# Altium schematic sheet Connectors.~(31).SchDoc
size A4
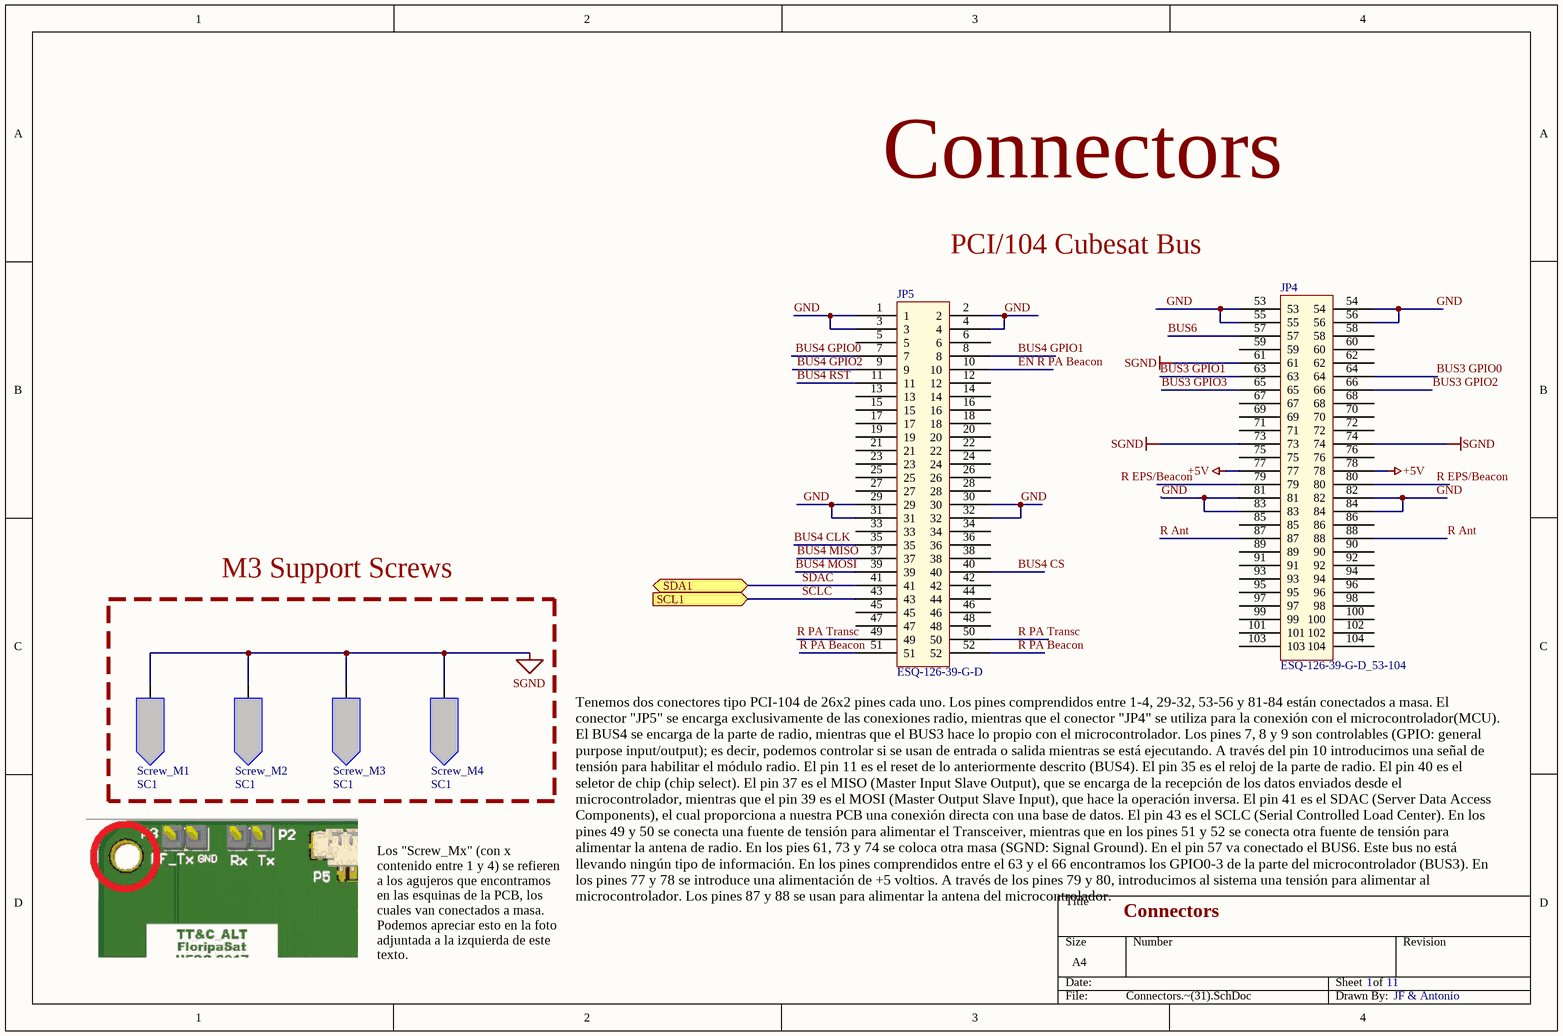
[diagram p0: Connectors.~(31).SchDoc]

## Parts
JP4  ESQ-126-39-G-D_53-104  [ESQ-126-39-G-D_53_104]
JP5  ESQ-126-39-G-D  [ESQ-126-39-G-D]
Screw_M1  SC1  [Screw_M3]
Screw_M2  SC1  [Screw_M3]
Screw_M3  SC1  [Screw_M3]
Screw_M4  SC1  [Screw_M3]

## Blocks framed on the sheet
M3 Support Screws: Screw_M1-Screw_M4

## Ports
SCL1 (in), SDA1 (bidir)

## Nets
+5V: JP4.77 JP4.78
SGND: JP4.61 JP4.73 JP4.74 Screw_M1.1 Screw_M2.1 Screw_M3.1 Screw_M4.1
BUS3 GPIO0: JP4.64
BUS3 GPIO1: JP4.63
BUS3 GPIO2: JP4.66
BUS3 GPIO3: JP4.65
BUS4 CLK: JP5.35
BUS4 CS: JP5.40
BUS4 GPIO0: JP5.7
BUS4 GPIO1: JP5.8
BUS4 GPIO2: JP5.9
BUS4 MISO: JP5.37
BUS4 MOSI: JP5.39
BUS4 RST: JP5.11
BUS6: JP4.57
EN R PA Beacon: JP5.10
GND: JP4.53 JP4.54 JP4.55 JP4.56 JP4.81 JP4.82 JP4.83 JP4.84 JP5.1 JP5.2 JP5.3 JP5.4 JP5.29 JP5.30 JP5.31 JP5.32
R Ant: JP4.87 JP4.88
R EPS/Beacon: JP4.80
R PA Beacon: JP5.51 JP5.52
R PA Transc: JP5.49 JP5.50
SCLC: JP5.43 ; port SCL1
SDAC: JP5.41 ; port SDA1

Not connected (* = marked no-connect by the designer): JP4 58 59 60 62 67 68 69 70 71 72 75 76 79 85 86 89 90 91 92 93 94 95 96 97 98 99 100 101 102 103 104; JP5 5 6 12 13 14 15 16 17 18 19 20 21 22 23 24 25 26 27 28 33 34 36 38 42 44 45 46 47 48

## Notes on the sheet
- Connectors
- PCI/104 Cubesat Bus
- Los "Screw_Mx" (con x contenido entre 1 y 4) se refieren a los agujeros que encontramos en las esquinas de la PCB, los cuales van conectados a masa. Podemos apreciar esto en la foto adjuntada a la izquierda de este texto.
- Tenemos dos conectores tipo PCI-104 de 26x2 pines cada uno. Los pines comprendidos entre 1-4, 29-32, 53-56 y 81-84 están conectados a masa. El conector "JP5" se encarga exclusivamente de las conexiones radio, mientras que el conector "JP4" se utiliza para la conexión con el microcontrolador(MCU). El BUS4 se encarga de la parte de radio, mientras que el BUS3 hace lo propio con el microcontrolador. Los pines 7, 8 y 9 son controlables (GPIO: general purpose input/output); es decir, podemos controlar si se usan de entrada o salida mientras se está ejecutando. A través del pin 10 introducimos una señal de tensión para habilitar el módulo radio. El pin 11 es el reset de lo anteriormente descrito (BUS4). El pin 35 es el reloj de la parte de radio. El pin 40 es el seletor de chip (chip select). El pin 37 es el MISO (Master Input Slave Output), que se encarga de la recepción de los datos enviados desde el microcontrolador, mientras que el pin 39 es el MOSI (Master Output Slave Input), que hace la operación inversa. El pin 41 es el SDAC (Server Data Access Components), el cual proporciona a nuestra PCB una conexión directa con una base de datos. El pin 43 es el SCLC (Serial Controlled Load Center). En los pines 49 y 50 se conecta una fuente de tensión para alimentar el Transceiver, mientras que en los pines 51 y 52 se conecta otra fuente de tensión para alimentar la antena de radio. En los pies 61, 73 y 74 se coloca otra masa (SGND: Signal Ground). En el pin 57 va conectado el BUS6. Este bus no está llevando ningún tipo de información. En los pines comprendidos entre el 63 y el 66 encontramos los GPIO0-3 de la parte del microcontrolador (BUS3). En los pines 77 y 78 se introduce una alimentación de +5 voltios. A través de los pines 79 y 80, introducimos al sistema una tensión para alimentar al microcontrolador. Los pines 87 y 88 se usan para alimentar la antena del microcontrolador.
- 1
- 11
- JF & Antonio
- Labels drawn without touching a wire or pin: R EPS/Beacon

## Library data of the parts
JP4 = ESQ-126-39-G-D_53-104: Cubesat Header Connector; Shop: es.rs-online.com; Localización: Último cajón cajonera blanca entre Pablo y Luis; Reference: 254-6132
JP5 = ESQ-126-39-G-D: Cubesat Header Connector; Shop: es.rs-online.com; Localización: Último cajón cajonera blanca entre Pablo y Luis; Reference: 254-6132
Screw_M1-Screw_M4 = Screw_M3: Main CubeSAT bus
